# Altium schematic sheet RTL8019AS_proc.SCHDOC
size A4; PageSetup: Record=PageOptions|SelectedOnly=False|CenterHorizontal=True|CenterVertical=True|PrintScale=0.92|XCorrection=1.00|YCorrection=1.00|PrintKind=1|BorderSize=5000000|LeftOffset=0|BottomOffset=0|Orientation=2|PaperLength=1000|PaperWidth=1000|Scale=100|PaperSource=7|PrintQuality=-4|MediaType=1|DitherType=10|PaperKind=Letter, 8,5x11 cali|PrintScaleMode=1
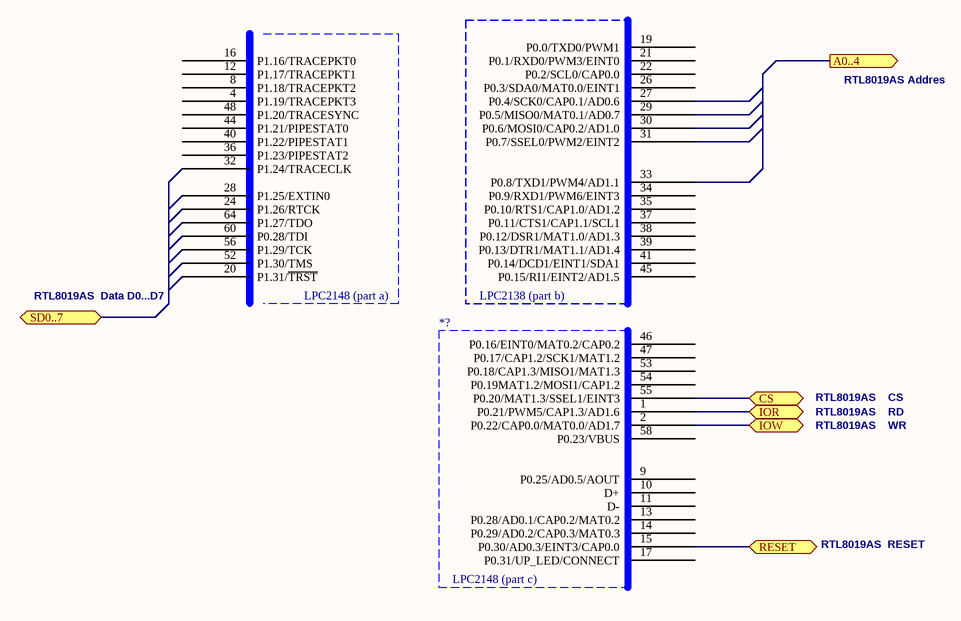
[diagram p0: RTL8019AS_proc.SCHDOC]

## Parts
(Parts that share a designator on the sheet are numbered #1, #2 ... from top to bottom, then left to right.)
*?#1  LPC_RIGHT_UP  (value not drawn)
*?#2  *  (value not drawn)
*?#3  (no value)

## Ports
A0..4 (out), CS, IOR, IOW, RESET, SD0..7

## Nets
CS: *?#3.55(P0.20/MAT1.3/SSEL1/EINT3) ; port CS
IOR: *?#3.1(P0.21/PWM5/CAP1.3/AD1.6) ; port IOR
IOW: *?#3.2(P0.22/CAP0.0/MAT0.0/AD1.7) ; port IOW
RESET: *?#3.15(P0.30/AD0.3/EINT3/CAP0.0) ; port RESET

Not connected (* = marked no-connect by the designer): *?#1 19(P0.0/TXD0/PWM1) 21(P0.1/RXD0/PWM3/EINT0) 22(P0.2/SCL0/CAP0.0) 26(P0.3/SDA0/MAT0.0/EINT1) 27(P0.4/SCK0/CAP0.1/AD0.6) 29(P0.5/MISO0/MAT0.1/AD0.7) 30(P0.6/MOSI0/CAP0.2/AD1.0) 31(P0.7/SSEL0/PWM2/EINT2) 33(P0.8/TXD1/PWM4/AD1.1) 34(P0.9/RXD1/PWM6/EINT3) 35(P0.10/RTS1/CAP1.0/AD1.2) 37(P0.11/CTS1/CAP1.1/SCL1) 38(P0.12/DSR1/MAT1.0/AD1.3) 39(P0.13/DTR1/MAT1.1/AD1.4) 41(P0.14/DCD1/EINT1/SDA1) 45(P0.15/RI1/EINT2/AD1.5); *?#2 4(P1.19/TRACEPKT3) 8(P1.18/TRACEPKT2) 12(P1.17/TRACEPKT1) 16(P1.16/TRACEPKT0) 20(P1.31/~{TRST}) 24(P1.26/RTCK) 28(P1.25/EXTIN0) 32(P1.24/TRACECLK) 36(P1.23/PIPESTAT2) 40(P1.22/PIPESTAT1) 44(P1.21/PIPESTAT0) 48(P1.20/TRACESYNC) 52(P1.30/TMS) 56(P1.29/TCK) 60(P0.28/TDI) 64(P1.27/TDO); *?#3 9(P0.25/AD0.5/AOUT) 10(D+) 11(D-) 13(P0.28/AD0.1/CAP0.2/MAT0.2) 14(P0.29/AD0.2/CAP0.3/MAT0.3) 17(P0.31/UP_LED/CONNECT) 46(P0.16/EINT0/MAT0.2/CAP0.2) 47(P0.17/CAP1.2/SCK1/MAT1.2) 53(P0.18/CAP1.3/MISO1/MAT1.3) 54(P0.19MAT1.2/MOSI1/CAP1.2) 58(P0.23/VBUS)

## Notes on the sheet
- RTL8019AS Addres
- RTL8019AS  Data D0...D7
- RTL8019AS    RD
- RTL8019AS    CS
- RTL8019AS    WR
- RTL8019AS  RESET

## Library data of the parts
*?#2 = LPC_left
*?#3 = LPC_RIGHT_DOWN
